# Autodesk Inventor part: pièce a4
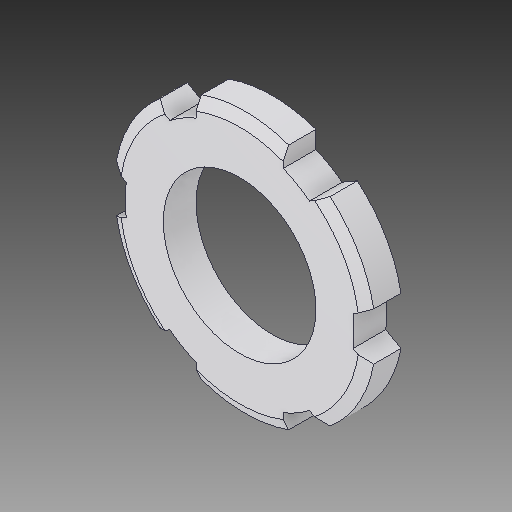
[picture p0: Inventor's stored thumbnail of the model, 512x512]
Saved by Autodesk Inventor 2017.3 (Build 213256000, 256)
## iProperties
Created: 2007-12
Part Number: pièce a4
Material: solidworks materials|Alliage 7079|22
Document SubType Name: Modeling
Designer: ficho
Appearance: 227,227,233
Author: ficho
Sending System: SolidWorks 2009
Last Author: christophe
Last Saved: 2011-01-23
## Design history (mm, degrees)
feature "Chanfrein2"
node "Solide1"
